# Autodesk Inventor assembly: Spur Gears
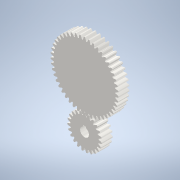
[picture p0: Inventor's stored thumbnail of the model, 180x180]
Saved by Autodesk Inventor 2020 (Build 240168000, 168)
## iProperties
ClientObjectVersion: 1
Created: 2019-09
Part Number: Spur Gears
Document SubType Name: Assembly
Designer: user
Categories: <?xml version="1.0" encoding="UTF-16"?> <MemberInstance><Categories><FamilyTemplate/><ParamToTemplateMap><ParamToTemplate><ParamToTemplate CategoryParameter="//
Author: user
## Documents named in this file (3)
- C:\Users\user\Documents\EIA\Cursos\Diseño asistido por computador\Parcial\2019-II\Archivos BancoDP  video Youtube\Ensamble\Design Accelerator\Spur Gears1.iam
- C:\Users\user\Documents\EIA\Cursos\Diseño asistido por computador\Parcial\2019-II\Archivos BancoDP  video Youtube\Ensamble\Design Accelerator\Spur Gear11.ipt
- C:\Users\user\Documents\EIA\Cursos\Diseño asistido por computador\Parcial\2019-II\Archivos BancoDP  video Youtube\Ensamble\Design Accelerator\Spur Gear21.ipt
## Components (2 placed, 2 different names)
1. Spur Gear1:1 — Rotation:1
2. Spur Gear2:1 — Rotation:1
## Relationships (1: RelateRotation 1)
- Rotation:1 [RelateRotation]: Spur Gear1:1 ↔ Spur Gear2:1
